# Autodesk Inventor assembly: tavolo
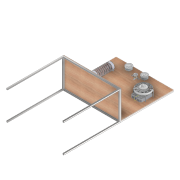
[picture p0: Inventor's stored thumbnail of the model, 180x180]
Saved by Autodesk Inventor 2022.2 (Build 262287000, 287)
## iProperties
_SolveAssemblyDoc: Frame Generator Solve Assembly
_Version: 25.0.0
Created: 2025-02
Part Number: tavolo
Document SubType Name: Assembly
Designer: 18907419
Author: 18907419
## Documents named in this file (12)
- C:\Users\18907419\Desktop\frigo\tavolo.iam
- C:\Users\18907419\Desktop\frigo\telaio_3D.ipt
- C:\Users\18907419\Desktop\frigo\tavolo\Frame\Frame 1740559699060.iam
- C:\Users\18907419\Desktop\frigo\piano_v.ipt
- C:\Users\18907419\Desktop\frigo\160620 compressor.ipt
- C:\Users\18907419\Desktop\frigo\Alphacool NexXxoS XT45 180mm Single.iam
- C:\Users\18907419\Desktop\frigo\001.001.00009.ipt
- C:\Users\18907419\Desktop\frigo\DML 052.ipt
- C:\Users\18907419\Desktop\frigo\Pièce2.ipt
- C:\Users\18907419\Desktop\frigo\Assemblage2 vert.iam
- C:\Users\18907419\Desktop\frigo\BML12S - 1-2in.ipt
- C:\Users\18907419\Desktop\frigo\Manômetro 7 bar.ipt
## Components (13 placed, 11 different names)
1. telaio_3D:1
2. Frame 1740559699060:1 [sub-assembly] — Allineato:1, Allineato:2, Allineato:3
3. piano_v:1 — Allineato:1, Allineato:2, Allineato:3, Coincidente:1, Coincidente:3, Coincidente:4, Coincidente:9, Coincidente:10, Angolo:1, Angolo:2
4. 160620 compressor:1 — Coincidente:1, Rotazionale:1
5. Alphacool NexXxoS XT45 180mm Single:1 [sub-assembly] — Coincidente:3
6. 001.001.00009:1 — Coincidente:4
7. DML 052:1 — Rotazionale:1
8. Pièce2:1
9. Pièce2:2 — Coincidente:9
10. Assemblage2 vert:1 [sub-assembly]
11. BML12S - 1-2in:1 — Coincidente:10
12. Manômetro 7 bar:1
13. Manômetro 7 bar:3
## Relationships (11: Mate 5, Flush 3, Angle 2, RevoluteJoint 1)
- Allineato:1 [Flush]: Frame 1740559699060:1 ↔ piano_v:1
- Allineato:2 [Flush]: Frame 1740559699060:1 ↔ piano_v:1
- Allineato:3 [Flush]: Frame 1740559699060:1 ↔ piano_v:1
- Coincidente:1 [Mate]: piano_v:1 ↔ 160620 compressor:1
- Coincidente:3 [Mate]: piano_v:1 ↔ Alphacool NexXxoS XT45 180mm Single:1
- Coincidente:4 [Mate]: piano_v:1 ↔ 001.001.00009:1
- Rotazionale:1 [RevoluteJoint]: 160620 compressor:1 ↔ DML 052:1
- Coincidente:9 [Mate]: piano_v:1 ↔ Pièce2:2
- Coincidente:10 [Mate]: piano_v:1 ↔ BML12S - 1-2in:1
- Angolo:1 [Angle]: piano_v:1
- Angolo:2 [Angle]: piano_v:1
## Named parameters: d12_d0 = 0, d13_d1 = 0, d14_d3 = 0
